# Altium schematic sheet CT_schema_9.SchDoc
size 278 x 170 mm
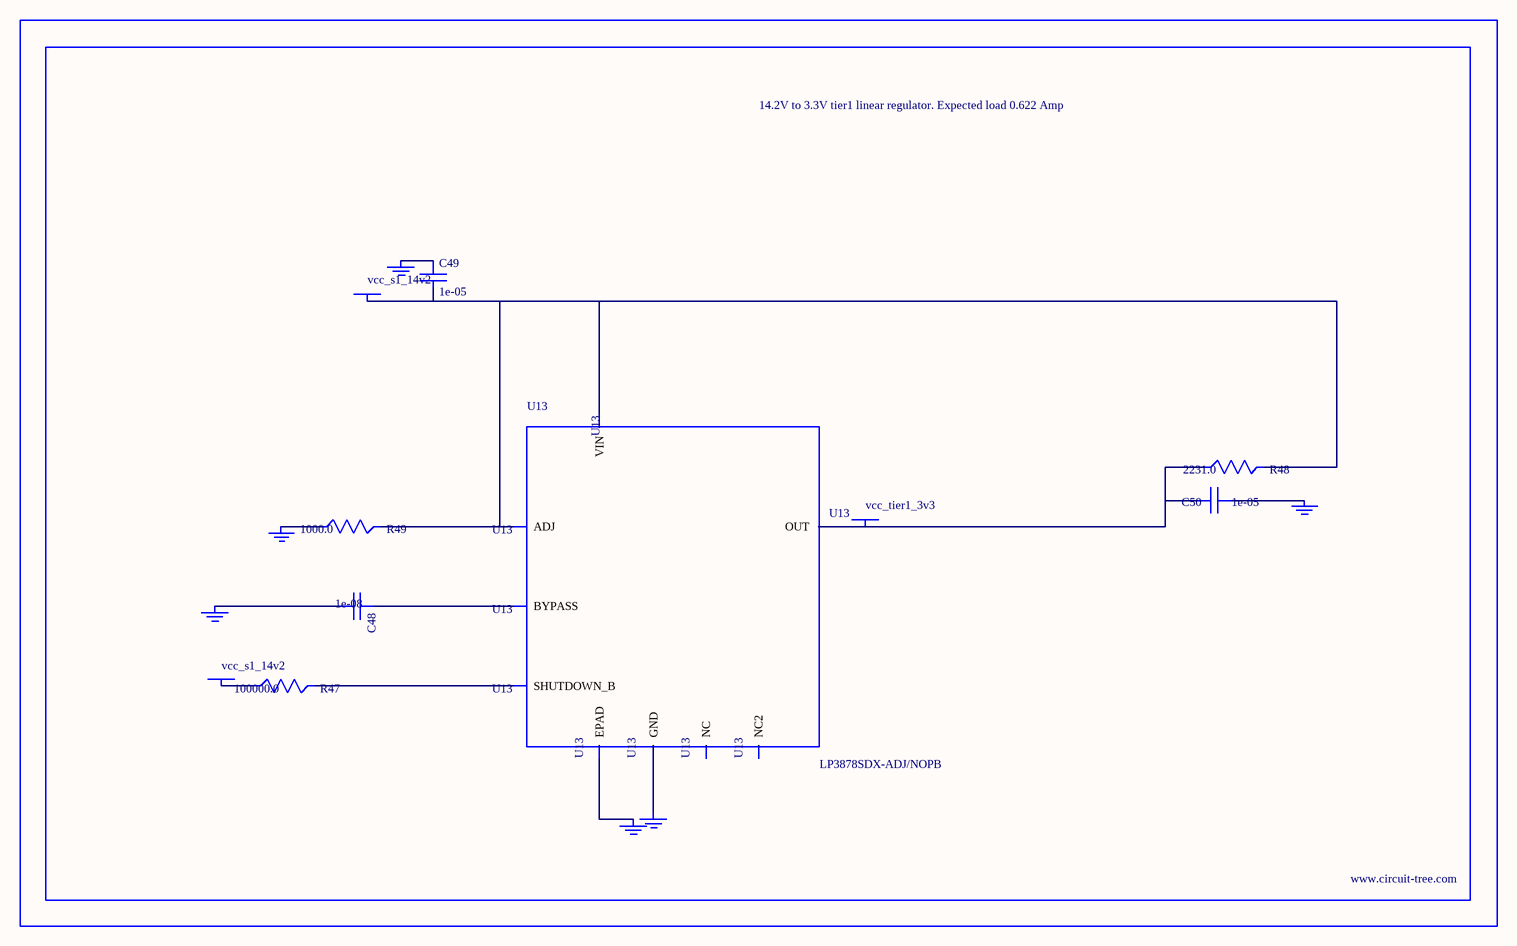
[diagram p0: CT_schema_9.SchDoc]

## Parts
BORDER8  (no value)
C48  1e-08  [C0402]
C49  1e-05  [C1210]
C50  1e-05  [C1210]
GND_INSTANCE_8_0  (no value)
GND_INSTANCE_8_1  (no value)
GND_INSTANCE_8_2  (no value)
GND_INSTANCE_8_3  (no value)
GND_INSTANCE_8_4  (no value)
GND_INSTANCE_8_5  (no value)
POWER_INSTANCE_8_0  vcc_s1_14v2
POWER_INSTANCE_8_1  vcc_s1_14v2
POWER_INSTANCE_8_2  vcc_tier1_3v3
R47  100000.0  [R0603]
R48  2231.0  [R0603]
R49  1000.0  [R0603]
U13  LP3878SDX-ADJ/NOPB  [WSON-8]

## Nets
NetC48_1: C48.1 U13.1(BYPASS)
NetC48_2: C48.2 GND_INSTANCE_8_0.0(GND)
NetC49_1: C49.1 GND_INSTANCE_8_1.0(GND)
NetC49_2: C49.2 POWER_INSTANCE_8_0.0(PWR) R48.2 R49.2 U13.4(VIN) U13.6(ADJ)
NetC50_1: C50.1 GND_INSTANCE_8_2.0(GND)
NetC50_2: C50.2 POWER_INSTANCE_8_2.0(PWR) R48.1 U13.5(OUT)
NetGND_INSTANCE_8_3_0: GND_INSTANCE_8_3.0(GND) R49.1
NetGND_INSTANCE_8_4_0: GND_INSTANCE_8_4.0(GND) U13.PAD(EPAD)
NetGND_INSTANCE_8_5_0: GND_INSTANCE_8_5.0(GND) U13.3(GND)
NetPOWER_INSTANCE_8_1_0: POWER_INSTANCE_8_1.0(PWR) R47.1
NetR47_2: R47.2 U13.8(SHUTDOWN_B)

Not connected (* = marked no-connect by the designer): U13 2(NC) 7(NC2)

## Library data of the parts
BORDER8 = BORDER_PAGE8
C48 = C0402C103K3RAC
C49 = C1210C106K5PACTU
C50 = GRM32DR61E106MA12L
GND_INSTANCE_8_0-GND_INSTANCE_8_5 = GND
POWER_INSTANCE_8_0-POWER_INSTANCE_8_2 = PWR
R47 = RC0603JR-07100KL
R48 = R48
R49 = RC0603JR-071KL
